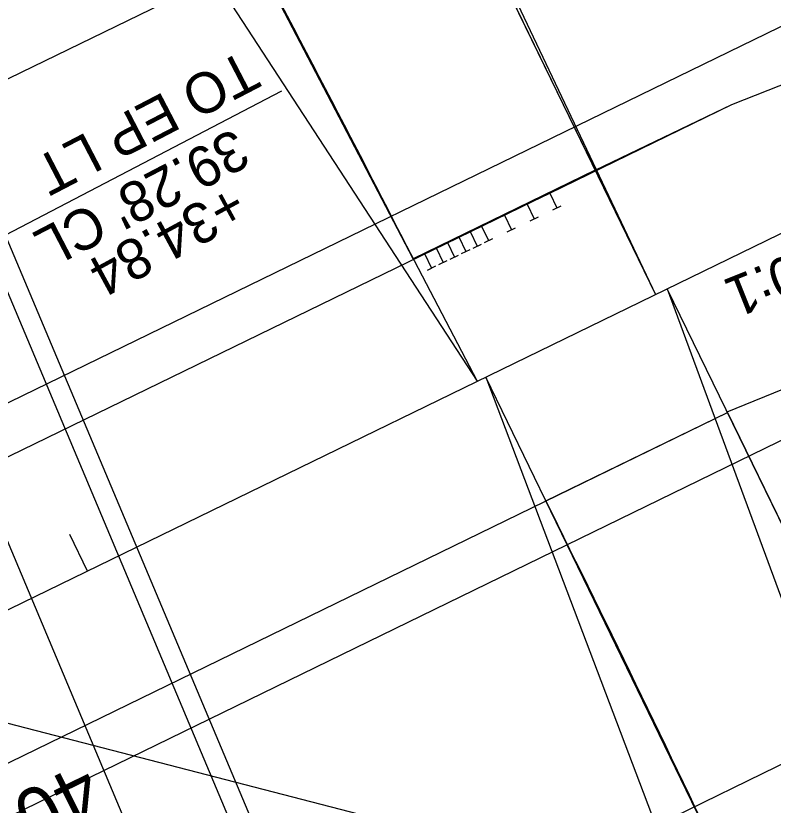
# Model space of a CAD drawing. Extents: x 2389694 to 2405615, y 546931 to 573532.
# Drawn here: x 2402527.9 to 2402621.6, y 570982.2 to 571079.7 of the extents above; entities that cross this region are included whole.
import ezdxf

# ---------------------------------------------------------------- set-up
doc = ezdxf.new("R2010")
doc.units = 0
for name, color, linetype in [('Old_Level_11', 7, 'Continuous'), ('Old_Level_3', 7, 'Continuous'), ('Prop Approach Slab', 7, 'Continuous'), ('Prop Approach Slab Hatching', 7, 'Continuous'), ('Prop Conc 2ft 6in Curb and Gutter', 7, 'Continuous'), ('Prop Conc 5in Monolithic Keyed In Island', 7, 'Continuous'), ('Prop Dimension', 7, 'Continuous'), ('Prop Dimension Text', 7, 'Continuous'), ('Prop EOT', 7, 'Continuous'), ('Prop Guardrail', 7, 'Continuous'), ('Prop Horizontal Alignment', 7, 'Continuous'), ('Prop Horizontal Alignment Curve and Spiral Data', 7, 'Continuous'), ('Prop Horizontal Alignment Tick Small', 7, 'Continuous'), ('Prop Lane Lines', 7, 'Continuous'), ('Prop SAU III Approach CELL', 7, 'Continuous')]:
    doc.layers.add(name, color=color, linetype=linetype)

msp = doc.modelspace()

# ---------------------------------------------------------------- linework, layer by layer
at = {"layer": 'Old_Level_3'}
msp.add_line((2402526.719, 571052.414), (2402619.911, 570831.283), dxfattribs=at)
at = {"layer": 'Prop Approach Slab'}
for p, q in [((2402398.277, 570962.561), (2402599.583, 571060.546)), ((2402414.146, 570932.472), (2402615.914, 571030.681))]:
    msp.add_line(p, q, dxfattribs=at)
for centre, start, end in [((2399937.214, 569701.599), 27.051356, 28.095592), ((2399938.301, 569702.128), 25.350253, 26.394078)]:
    msp.add_arc(centre, 2964.133, start, end, dxfattribs=at)
at = {"layer": 'Prop Approach Slab Hatching'}
for points in [[(2402552.063, 571097.539), (2402575.923, 571109.154), (2402599.557, 571060.6), (2402577.069, 571049.654)], [(2402593.473, 571019.757), (2402615.914, 571030.681), (2402639.521, 570982.181), (2402617.08, 570971.258)]]:
    msp.add_lwpolyline(points, close=True, dxfattribs=at)
at = {"layer": 'Prop Conc 2ft 6in Curb and Gutter'}
msp.add_line((2402526.719, 571052.414), (2402605.967, 570864.369), dxfattribs=at)
at = {"layer": 'Prop Conc 5in Monolithic Keyed In Island'}
msp.add_spline([(2402502.707, 570998.434), (2402503.103, 570997.628), (2402503.499, 570996.821), (2402503.895, 570996.014), (2402504.29, 570995.207), (2402504.685, 570994.4), (2402505.085, 570993.583), (2402505.479, 570992.776), (2402505.874, 570991.968), (2402506.268, 570991.161), (2402506.662, 570990.353), (2402507.056, 570989.545), (2402507.449, 570988.737), (2402507.842, 570987.929), (2402508.235, 570987.121), (2402508.628, 570986.312), (2402509.02, 570985.504), (2402509.417, 570984.686), (2402509.809, 570983.878), (2402510.201, 570983.069), (2402510.592, 570982.26), (2402510.983, 570981.451), (2402511.374, 570980.642), (2402511.765, 570979.832), (2402512.155, 570979.023), (2402512.545, 570978.213), (2402512.935, 570977.404), (2402513.325, 570976.594), (2402513.718, 570975.775), (2402514.107, 570974.965), (2402514.496, 570974.155), (2402514.885, 570973.345), (2402515.273, 570972.534), (2402515.661, 570971.723), (2402516.049, 570970.913), (2402516.437, 570970.102), (2402516.824, 570969.291), (2402517.211, 570968.48), (2402517.598, 570967.669), (2402517.989, 570966.849), (2402518.375, 570966.038), (2402518.761, 570965.226), (2402519.147, 570964.415), (2402519.533, 570963.603), (2402519.918, 570962.791), (2402520.303, 570961.979), (2402520.688, 570961.167), (2402521.072, 570960.355), (2402521.456, 570959.543), (2402521.84, 570958.731), (2402522.229, 570957.909), (2402522.612, 570957.096), (2402522.996, 570956.284), (2402523.379, 570955.471), (2402523.761, 570954.658), (2402524.144, 570953.845), (2402524.526, 570953.032), (2402524.908, 570952.218), (2402525.29, 570951.405), (2402525.671, 570950.591), (2402526.053, 570949.777), (2402526.433, 570948.964), (2402526.818, 570948.141), (2402527.199, 570947.327), (2402527.579, 570946.513), (2402527.959, 570945.699), (2402528.339, 570944.884), (2402528.718, 570944.069), (2402529.097, 570943.255), (2402529.476, 570942.44), (2402529.855, 570941.625), (2402530.233, 570940.811), (2402530.611, 570939.995), (2402530.993, 570939.171), (2402531.371, 570938.356)], degree=3, dxfattribs=at)
at = {"layer": 'Prop Dimension'}
for p, q in [((2402575.968, 571110.59), (2402607.023, 571045.26)), ((2402575.923, 571109.154), (2402607.023, 571045.26)), ((2402538.587, 571105.681), (2402584.969, 571034.525)), ((2402552.063, 571097.539), (2402584.969, 571034.525)), ((2402524.416, 571051.441), (2402560.806, 571070.423)), ((2402639.521, 570982.181), (2402608.474, 571045.966)), ((2402608.474, 571045.966), (2402631.063, 570984.665)), ((2402617.01, 570971.224), (2402586.055, 571035.054)), ((2402586.055, 571035.054), (2402616.896, 570953.631))]:
    msp.add_line(p, q, dxfattribs=at)
at = {"layer": 'Prop EOT'}
for p, q in [((2401929.01, 570740.823), (2403785.549, 571644.477)), ((2401949.142, 570699.462), (2403805.681, 571603.116)), ((2402385.968, 570872.046), (2403551.693, 571439.452)), ((2402349.251, 570985.409), (2402780.734, 571195.43)), ((2402616.462, 571068.71), (2402761.846, 571126.9)), ((2402599.557, 571060.6), (2402616.462, 571068.71)), ((2402524.416, 571051.443), (2402617.607, 570830.312)), ((2402615.879, 571030.753), (2402644.889, 571042.559))]:
    msp.add_line(p, q, dxfattribs=at)
at = {"layer": 'Prop Guardrail'}
for p, q in [((2402616.462, 571068.71), (2402761.846, 571126.9)), ((2402593.974, 571057.764), (2402616.462, 571068.71))]:
    msp.add_line(p, q, dxfattribs=at)
at = {"layer": 'Prop Horizontal Alignment'}
msp.add_line((2401939.076, 570720.142), (2404036.593, 571741.091), dxfattribs=at)
msp.add_arc((2399929.798, 569697.989), 2887.133, 22.844769, 37.679361, dxfattribs=at)
at = {"layer": 'Prop Horizontal Alignment Curve and Spiral Data'}
msp.add_line((2402508.129, 570997.124), (2402611.835, 570970.392), dxfattribs=at)
at = {"layer": 'Prop Horizontal Alignment Tick Small'}
msp.add_line((2402536.812, 571011.085), (2402534.624, 571015.581), dxfattribs=at)
at = {"layer": 'Prop Lane Lines'}
msp.add_line((2402513.776, 571045.893), (2402765.475, 570448.527), dxfattribs=at)
msp.add_spline([(2402542.203, 570943.52), (2402541.824, 570944.339), (2402541.44, 570945.167), (2402541.06, 570945.985), (2402540.68, 570946.803), (2402540.3, 570947.622), (2402539.919, 570948.44), (2402539.539, 570949.258), (2402539.158, 570950.076), (2402538.776, 570950.893), (2402538.395, 570951.711), (2402538.013, 570952.528), (2402537.631, 570953.346), (2402537.244, 570954.172), (2402536.862, 570954.989), (2402536.479, 570955.806), (2402536.096, 570956.623), (2402535.712, 570957.44), (2402535.329, 570958.257), (2402534.945, 570959.073), (2402534.561, 570959.89), (2402534.176, 570960.706), (2402533.792, 570961.522), (2402533.407, 570962.338), (2402533.022, 570963.154), (2402532.632, 570963.979), (2402532.246, 570964.795), (2402531.86, 570965.611), (2402531.474, 570966.426), (2402531.088, 570967.242), (2402530.701, 570968.057), (2402530.314, 570968.872), (2402529.927, 570969.687), (2402529.539, 570970.502), (2402529.152, 570971.317), (2402528.764, 570972.132), (2402528.371, 570972.955), (2402527.983, 570973.77), (2402527.594, 570974.584), (2402527.205, 570975.398), (2402526.816, 570976.212), (2402526.426, 570977.026), (2402526.036, 570977.84), (2402525.647, 570978.654), (2402525.256, 570979.467), (2402524.866, 570980.281), (2402524.475, 570981.094), (2402524.079, 570981.917), (2402523.688, 570982.73), (2402523.297, 570983.542), (2402522.905, 570984.356), (2402522.513, 570985.168), (2402522.121, 570985.981), (2402521.728, 570986.794), (2402521.335, 570987.606), (2402520.942, 570988.418), (2402520.549, 570989.231), (2402520.155, 570990.042), (2402519.757, 570990.863), (2402519.363, 570991.675), (2402518.968, 570992.487), (2402518.574, 570993.299), (2402518.179, 570994.11), (2402517.784, 570994.921), (2402517.388, 570995.733), (2402516.993, 570996.544), (2402516.597, 570997.355), (2402516.201, 570998.166), (2402515.805, 570998.976), (2402515.404, 570999.796), (2402515.007, 571000.606), (2402514.61, 571001.417), (2402514.212, 571002.227), (2402513.814, 571003.037), (2402513.416, 571003.847)], degree=3, dxfattribs=at)
at = {"layer": 'Prop SAU III Approach CELL'}
for p, q in [((2402577.069, 571049.654), (2402593.974, 571057.764)), ((2402593.974, 571057.764), (2402594.839, 571055.961)), ((2402591.157, 571056.412), (2402592.022, 571054.609)), ((2402594.322, 571055.713), (2402595.355, 571056.209)), ((2402588.339, 571055.061), (2402589.204, 571053.257)), ((2402591.505, 571054.362), (2402592.538, 571054.857)), ((2402585.521, 571053.709), (2402586.386, 571051.906)), ((2402588.688, 571053.01), (2402589.721, 571053.505)), ((2402584.112, 571053.033), (2402584.978, 571051.23)), ((2402581.295, 571051.681), (2402582.16, 571049.878)), ((2402582.704, 571052.357), (2402583.569, 571050.554)), ((2402585.87, 571051.658), (2402586.903, 571052.153)), ((2402579.886, 571051.005), (2402580.751, 571049.202)), ((2402583.053, 571050.306), (2402584.085, 571050.802)), ((2402584.461, 571050.982), (2402585.494, 571051.478)), ((2402578.477, 571050.329), (2402579.343, 571048.526)), ((2402581.644, 571049.63), (2402582.677, 571050.126)), ((2402578.826, 571048.279), (2402579.859, 571048.774)), ((2402580.235, 571048.954), (2402581.268, 571049.45))]:
    msp.add_line(p, q, dxfattribs=at)

# ---------------------------------------------------------------- texts
at = {"layer": 'Old_Level_11'}
for s, p in [('TO EP LT', (2402556.183, 571075.526)), ("39.28' CL", (2402554.984, 571065.883))]:
    msp.add_text(s, height=5, rotation=207.50471, dxfattribs=at).set_placement(p)
at = {"layer": 'Prop Dimension Text'}
for s, rotation, p in [('+34.84', 208.53871, (2402554.607, 571059.054)), ('50:1', 201.77577, (2402627.284, 571051.775))]:
    msp.add_text(s, height=5, rotation=rotation, dxfattribs=at).set_placement(p)
at = {"layer": 'Prop Horizontal Alignment Curve and Spiral Data'}
msp.add_text('40', height=7, rotation=206.25511, dxfattribs=at).set_placement((2402536.346, 570987.564))

doc.saveas('drawing.dxf')
